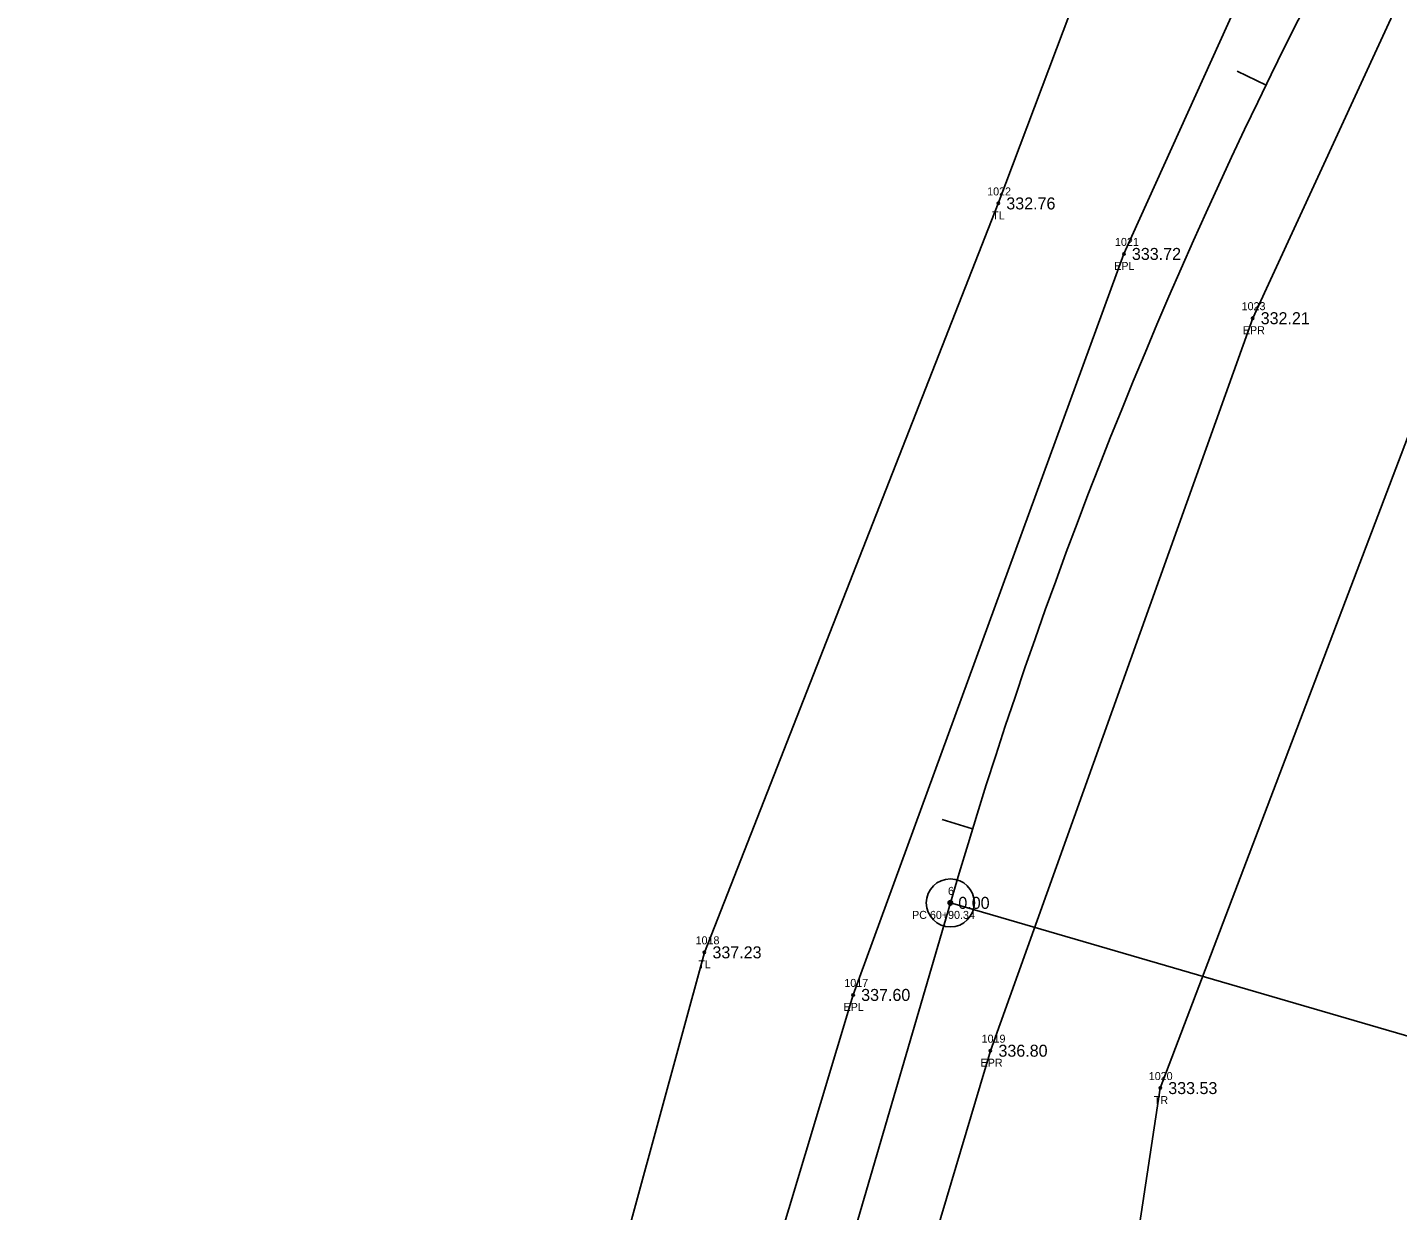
# Model space of a CAD drawing. Extents: x 2231119 to 2232595, y 1035731 to 1037094.
# Drawn here: x 2231141.6 to 2231312.8, y 1036013.8 to 1036161.6 of the extents above; entities that cross this region are included whole.
import ezdxf

# ---------------------------------------------------------------- set-up
doc = ezdxf.new("R2010")
doc.units = 0
for name, color, linetype in [('RD_EX_Road', 7, 'Continuous'), ('RD_EX_Road_txCode', 7, 'Continuous'), ('RD_EX_TX_Road_ELEV', 7, 'Continuous'), ('RD_EX_TX_VEG_ELEV', 7, 'Continuous'), ('RD_EX_VEG', 7, 'Continuous'), ('RD_EX_VEG_txCode', 7, 'Continuous'), ('RD_HC_Cl', 7, 'Continuous'), ('RD_HC_Data', 7, 'Continuous'), ('RD_HC_Data_Tic', 7, 'Continuous'), ('RD_HC_Survey_ELEV', 7, 'Continuous'), ('RD_HC_txCode', 7, 'Continuous'), ('RD_SMD_Locator', 7, 'Continuous')]:
    doc.layers.add(name, color=color, linetype=linetype)

msp = doc.modelspace()

# ---------------------------------------------------------------- linework, layer by layer
at = {"layer": 'RD_EX_Road'}
for points in [[(2231158.42, 1035748.11), (2231188.37, 1035851.38), (2231216.59, 1035946.92), (2231244.77, 1036040.72), (2231278.59, 1036133.31), (2231299.55, 1036179.73), (2231323.11, 1036221.2), (2231350.7, 1036262.3), (2231381.59, 1036299.29), (2231415.97, 1036336.9), (2231452.94, 1036369.74), (2231498.19, 1036405.3), (2231537.2, 1036432.57), (2231541.46, 1036424.96)], [(2231176.43, 1035742.89), (2231206.61, 1035845.83), (2231234.19, 1035940.65), (2231261.92, 1036033.75), (2231294.68, 1036125.28), (2231316.11, 1036171.75), (2231338.19, 1036211.09), (2231363.83, 1036252.38), (2231394.08, 1036289.28), (2231427.67, 1036324.2), (2231464.37, 1036355.5), (2231508.96, 1036392.41), (2231546.55, 1036416.22), (2231541.46, 1036424.96)]]:
    msp.add_lwpolyline(points, dxfattribs=at)
at = {"layer": 'RD_EX_VEG'}
for points in [[(2231141.61, 1035753.39), (2231172.54, 1035856.04), (2231200.09, 1035950.41), (2231226.19, 1036046.04), (2231262.9, 1036139.62), (2231281.03, 1036187.82), (2231303.66, 1036232.51), (2231318.61, 1036284.65), (2231353.84, 1036322.59), (2231394.02, 1036358.2), (2231443.85, 1036383.78)], [(2231211.01, 1035732.98), (2231244.87, 1035834.47), (2231267.87, 1035928.24), (2231283.13, 1036029.08), (2231316.25, 1036116.26), (2231338.15, 1036162.94), (2231357.98, 1036198.54), (2231413.07, 1036272.2), (2231445.22, 1036302.16), (2231483.09, 1036338.47), (2231530.02, 1036372.29)]]:
    msp.add_lwpolyline(points, dxfattribs=at)
at = {"layer": 'RD_HC_Cl'}
msp.add_line((2231167.43, 1035745.5), (2231256.91, 1036052.22), dxfattribs=at)
msp.add_arc((2231880.38, 1035870.33), 649.46, 120.68197, 163.7355, dxfattribs=at)
at = {"layer": 'RD_HC_Data'}
msp.add_line((2231256.91, 1036052.22), (2231368.89, 1036019.55), dxfattribs=at)
for radius in [3, 0.282]:
    msp.add_circle((2231256.91, 1036052.22), radius, dxfattribs=at)
at = {"layer": 'RD_HC_Data_Tic'}
for p, q in [((2231296.35, 1036154.41), (2231292.75, 1036156.16)), ((2231259.69, 1036061.48), (2231255.87, 1036062.66))]:
    msp.add_line(p, q, dxfattribs=at)
at = {"layer": 'RD_SMD_Locator'}
for centre in [(2231262.9, 1036139.62), (2231278.59, 1036133.31), (2231294.68, 1036125.28), (2231256.91, 1036052.22), (2231226.19, 1036046.04), (2231244.77, 1036040.72), (2231261.92, 1036033.75), (2231283.13, 1036029.08)]:
    msp.add_circle(centre, 0.15, dxfattribs=at)

# ---------------------------------------------------------------- texts
at = {"layer": 'RD_EX_Road_txCode'}
for s, p in [('1021', (2231277.48, 1036134.31)), ('EPL', (2231277.38, 1036131.31)), ('1023', (2231293.3, 1036126.28)), ('EPR', (2231293.45, 1036123.28)), ('1017', (2231243.67, 1036041.72)), ('EPL', (2231243.57, 1036038.72)), ('1019', (2231260.82, 1036034.75)), ('EPR', (2231260.69, 1036031.75))]:
    msp.add_text(s, height=1, dxfattribs=at).set_placement(p)
at = {"layer": 'RD_EX_TX_Road_ELEV'}
for s, p in [('333.72', (2231279.59, 1036132.56)), ('332.21', (2231295.68, 1036124.53)), ('337.60', (2231245.77, 1036039.97)), ('336.80', (2231262.92, 1036033))]:
    msp.add_text(s, height=1.5, dxfattribs=at).set_placement(p)
at = {"layer": 'RD_EX_TX_VEG_ELEV'}
for s, p in [('332.76', (2231263.9, 1036138.87)), ('337.23', (2231227.19, 1036045.29)), ('333.53', (2231284.13, 1036028.33))]:
    msp.add_text(s, height=1.5, dxfattribs=at).set_placement(p)
at = {"layer": 'RD_EX_VEG_txCode'}
for s, p in [('1022', (2231261.51, 1036140.62)), ('TL', (2231262.13, 1036137.62)), ('1018', (2231225.09, 1036047.04)), ('TL', (2231225.42, 1036044.04)), ('1020', (2231281.7, 1036030.08)), ('TR', (2231282.33, 1036027.08))]:
    msp.add_text(s, height=1, dxfattribs=at).set_placement(p)
at = {"layer": 'RD_HC_Survey_ELEV'}
msp.add_text('0.00', height=1.5, dxfattribs=at).set_placement((2231257.91, 1036051.47))
at = {"layer": 'RD_HC_txCode'}
for s, p in [('6', (2231256.61, 1036053.22)), ('PC 60+90.34', (2231252.13, 1036050.22))]:
    msp.add_text(s, height=1, dxfattribs=at).set_placement(p)

doc.saveas('drawing.dxf')
